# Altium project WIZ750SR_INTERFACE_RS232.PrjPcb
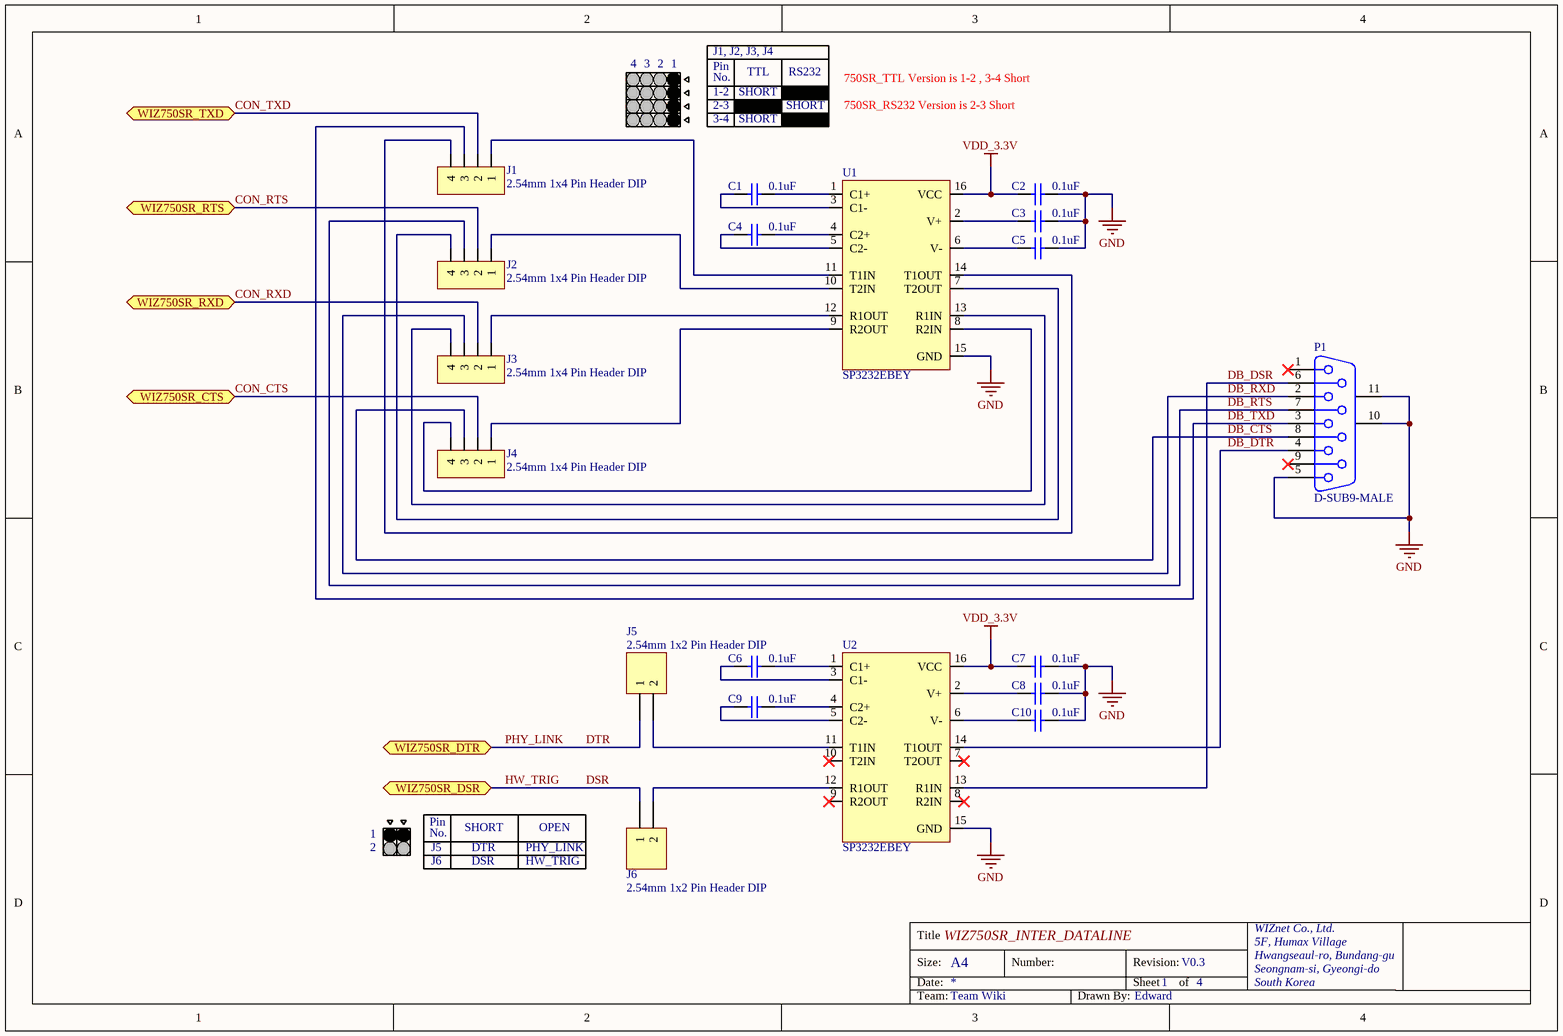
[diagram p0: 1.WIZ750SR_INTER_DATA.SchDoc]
4 sheets, 76 parts. Net scope: flat (ports and power ports of the same name join across sheets).
Board file: WIZ750SR_INTERFACE_RS232.PcbDoc
Sheets:
  1.WIZ750SR_INTER_DATA.SchDoc
  2.WIZ750SR_INTER_PWR_USB.SchDoc
  3.WIZ750SR_INTER_CON.SchDoc
  4.WIZ750SR_INTER_ETC.SchDoc

## Sheet 1.WIZ750SR_INTER_DATA.SchDoc
size A4; DrawnBy: Peter; Organization: WIZnet Co., Ltd.; Address1: 5F, Humax Village; Address2: Hwangseaul-ro, Bundang-Gu; Address3: Seongnam-Si, Gyeonggi-Do; Address4: South Korea; Team: Wiki

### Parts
C1  0.1uF  [CAP-0603]
C2  0.1uF  [CAP-0603]
C3  0.1uF  [CAP-0603]
C4  0.1uF  [CAP-0603]
C5  0.1uF  [CAP-0603]
C6  0.1uF  [CAP-0603]
C7  0.1uF  [CAP-0603]
C8  0.1uF  [CAP-0603]
C9  0.1uF  [CAP-0603]
C10  0.1uF  [CAP-0603]
J1  2.54mm 1x4 Pin Header DIP  [IDC-1X4]
J2  2.54mm 1x4 Pin Header DIP  [IDC-1X4]
J3  2.54mm 1x4 Pin Header DIP  [IDC-1X4]
J4  2.54mm 1x4 Pin Header DIP  [IDC-1X4]
J5  2.54mm 1x2 Pin Header DIP  [IDC-1X2]
J6  2.54mm 1x2 Pin Header DIP  [IDC-1X2]
P1  D-SUB9-MALE  [D-SUB9-MALE]
U1  SP3232EBEY  [SP3232EBEY-TSSOP16]
U2  SP3232EBEY  [SP3232EBEY-TSSOP16]

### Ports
WIZ750SR_CTS, WIZ750SR_DSR, WIZ750SR_DTR, WIZ750SR_RTS, WIZ750SR_RXD, WIZ750SR_TXD

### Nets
GND: C2.2 C3.2 C5.2 C7.2 C8.2 C10.2 P1.5 P1.10(MH1) P1.11(MH2) U1.15(GND) U2.15(GND)
VDD_3.3V: C2.1 C7.1 U1.16(VCC) U2.16(VCC)
CON_CTS: J4.2 ; port WIZ750SR_CTS
CON_RTS: J2.2 ; port WIZ750SR_RTS
CON_RXD: J3.2 ; port WIZ750SR_RXD
CON_TXD: J1.2 ; port WIZ750SR_TXD
DB_CTS: J4.3 P1.8
DB_DSR: P1.6 U2.13(R1IN)
DB_DTR: P1.4 U2.14(T1OUT)
DB_RTS: J2.3 P1.7
DB_RXD: J3.3 P1.2
DB_TXD: J1.3 P1.3
DSR: J6.1 ; port WIZ750SR_DSR  [also labelled HW_TRIG]
DTR: J5.1 ; port WIZ750SR_DTR  [also labelled PHY_LINK]
NetC1_1: C1.1 U1.3(C1-)
NetC1_2: C1.2 U1.1(C1+)
NetC3_1: C3.1 U1.2(V+)
NetC4_1: C4.1 U1.5(C2-)
NetC4_2: C4.2 U1.4(C2+)
NetC5_1: C5.1 U1.6(V-)
NetC6_1: C6.1 U2.3(C1-)
NetC6_2: C6.2 U2.1(C1+)
NetC8_1: C8.1 U2.2(V+)
NetC9_1: C9.1 U2.5(C2-)
NetC9_2: C9.2 U2.4(C2+)
NetC10_1: C10.1 U2.6(V-)
NetJ1_1: J1.1 U1.11(T1IN)
NetJ1_4: J1.4 U1.14(T1OUT)
NetJ2_1: J2.1 U1.10(T2IN)
NetJ2_4: J2.4 U1.7(T2OUT)
NetJ3_1: J3.1 U1.12(R1OUT)
NetJ3_4: J3.4 U1.13(R1IN)
NetJ4_1: J4.1 U1.9(R2OUT)
NetJ4_4: J4.4 U1.8(R2IN)
NetJ5_2: J5.2 U2.11(T1IN)
NetJ6_2: J6.2 U2.12(R1OUT)

Not connected (* = marked no-connect by the designer): P1 1* 9*; U2 7(T2OUT)* 8(R2IN)* 9(R2OUT)* 10(T2IN)*

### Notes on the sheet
- 4
- 3
- 2
- 1
- Pin
- 1-2
- 2-3
- No.
- J1, J2, J3, J4
- SHORT
- TTL
- RS232
- 750SR_TTL Version is 1-2 , 3-4 Short
- 750SR_RS232 Version is 2-3 Short
- 3-4
- J5
- DTR
- PHY_LINK
- OPEN
- J6
- DSR
- HW_TRIG
- Title
- Size:
- Date:
- WIZ750SR_INTER_DATALINE
- A4
- Number:
- Revision:
- Sheet
- of
- V0.3
- WIZnet Co., Ltd.
- 5F, Humax Village
- Hwangseaul-ro, Bundang-gu
- Seongnam-si, Gyeongi-do
- South Korea
- Team:
- Team Wiki
- Drawn By:
- Edward

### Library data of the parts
C1-C10 = CAP-0603: Ceramic CAP 0603(1608)
J5 J6 = Header 2: Header, 2-Pin
P1 = D-SUB9-MALE: D-SUB-9, MALE,  Right Angle; PackageDocument: O; Positions: 9; Gender: Receptacle
U1 U2 = SP3232EBEY: True +3.0V to +5.5V RS-232 Transceivers

## Sheet 2.WIZ750SR_INTER_PWR_USB.SchDoc
size A4; DrawnBy: Peter; Organization: WIZnet Co., Ltd.; Address1: 5F, Humax Village; Address2: Hwangseaul-ro, Bundang-Gu; Address3: Seongnam-Si, Gyeonggi-Do; Address4: South Korea; Team: Wiki
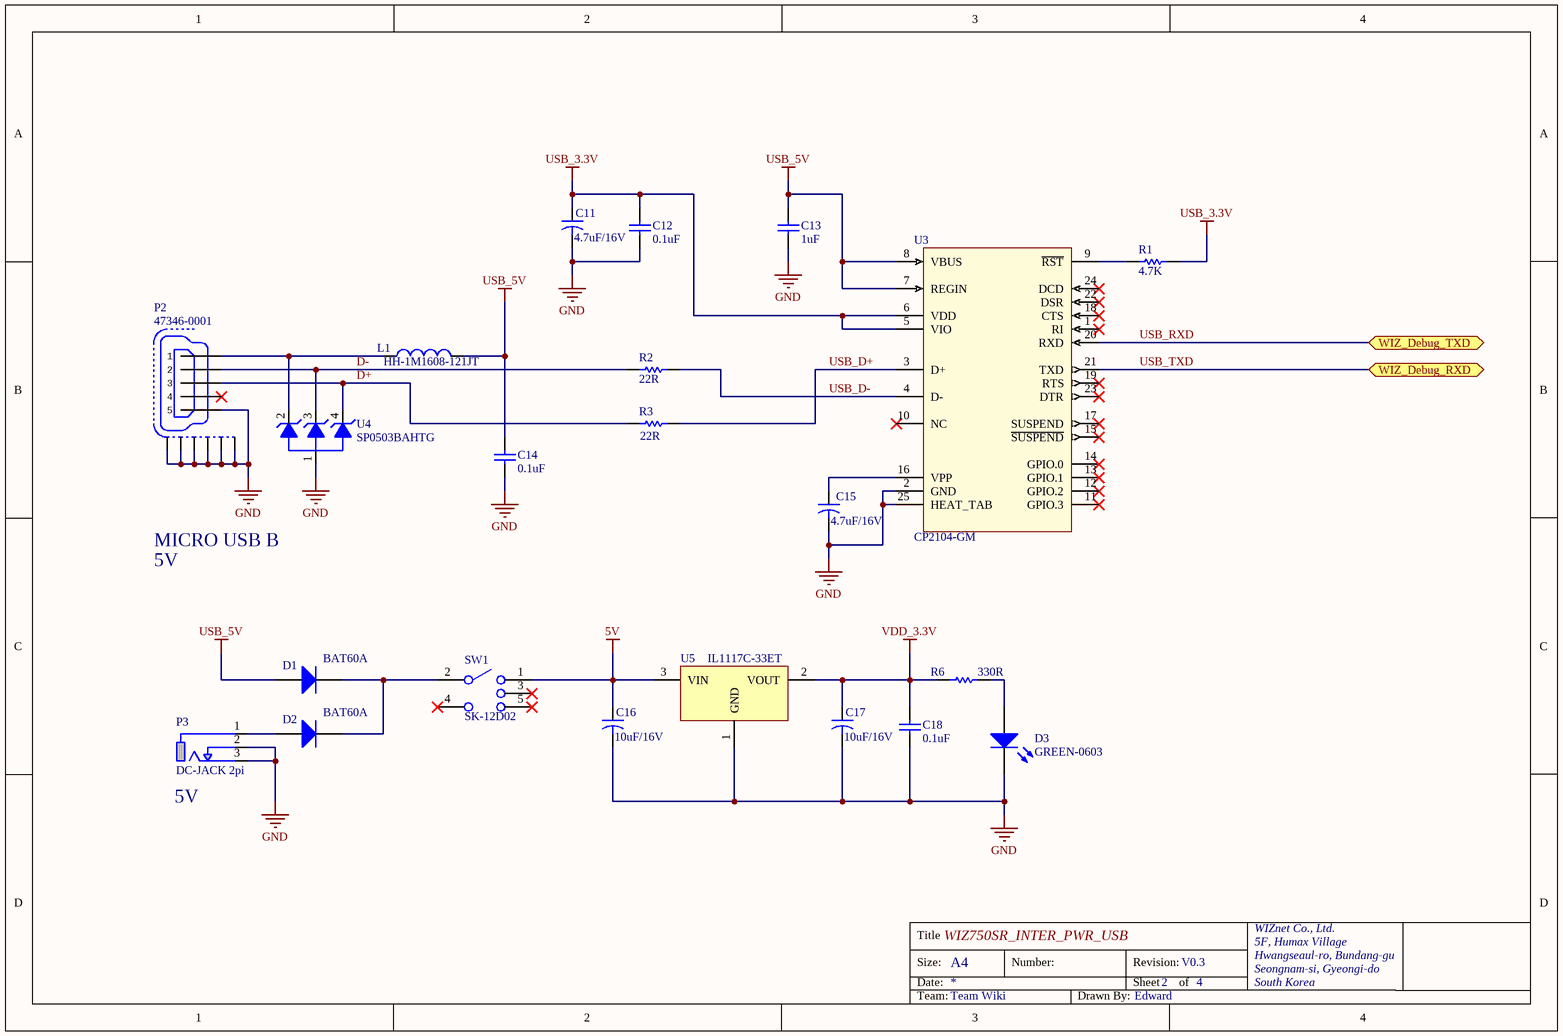
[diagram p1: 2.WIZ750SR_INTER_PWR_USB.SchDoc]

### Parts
C11  4.7uF/16V  [CAP-A Size]
C12  0.1uF  [CAP-0603]
C13  1uF  [CAP-0603]
C14  0.1uF  [CAP-0603]
C15  4.7uF/16V  [CAP-A Size]
C16  10uF/16V  [CAP-A Size]
C17  10uF/16V  [CAP-A Size]
C18  0.1uF  [CAP-0603]
D1  BAT60A  [D-BAT60A/SOD-323]
D2  BAT60A  [D-BAT60A/SOD-323]
D3  GREEN-0603  [LED-0603-RED]
L1  HH-1M1608-121JT  [IND-0603]
P2  47346-0001  [USB-MICRO-B(SMD)]
P3  DC-JACK 2pi  [DC-JACK 2pi]
R1  4.7K  [RES-0603]
R2  22R  [RES-0603]
R3  22R  [RES-0603]
R6  330R  [RES-0603]
SW1  SK-12D02  [SK-12D02]
U3  CP2104-GM  [CP2104_QFN24_PAD]
U4  SP0503BAHTG  [SP0503BAHTG]
U5  IL1117C-33ET  [IL1117C-33ET]

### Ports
WIZ_Debug_RXD, WIZ_Debug_TXD

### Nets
5V: C16.1 SW1.1 U5.3(VIN)
GND: C11.2 C12.1 C13.1 C14.1 C15.2 C16.2 C17.2 C18.1 D3.2(K) P2.5 P2.6 P2.7 P2.8 P2.9 P2.10 P2.11 P3.2(GND) P3.3(GND) U3.2(GND) U3.25(HEAT_TAB) U4.1 U5.1(GND)
USB_3.3V: C11.1 C12.2 R1.2 U3.5(VIO) U3.6(VDD)
USB_5V: C13.2 C14.2 D1.2(A) L1.2 U3.7(REGIN) U3.8(VBUS)
VDD_3.3V: C17.1 C18.2 R6.1 U5.2(VOUT)
D+: P2.3 R3.1 U4.4
D-: P2.2 R2.1 U4.3
USB_D+: R3.2 U3.3(D+)
USB_D-: R2.2 U3.4(D-)
USB_RXD: U3.20(RXD) ; port WIZ_Debug_TXD  [project net U_TXD]
USB_TXD: U3.21(TXD) ; port WIZ_Debug_RXD  [project net U_RXD]
NetC15_1: C15.1 U3.16(VPP)
NetD1_1: D1.1(K) D2.1(K) SW1.2
NetD2_2: D2.2(A) P3.1(VCC)
NetD3_1: D3.1(A) R6.2
NetL1_1: L1.1 P2.1 U4.2
NetR1_1: R1.1 U3.9(~{RST})

Not connected (* = marked no-connect by the designer): P2 4*; SW1 3* 4* 5*; U3 1(RI)* 10(NC)* 11(GPIO.3)* 12(GPIO.2)* 13(GPIO.1)* 14(GPIO.0)* 15(~{SUSPEND})* 17(SUSPEND)* 18(CTS)* 19(RTS)* 22(DSR)* 23(DTR)* 24(DCD)*

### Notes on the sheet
- MICRO USB B
- 5V
- (near P3) 5V
- Title
- Size:
- Date:
- WIZ750SR_INTER_PWR_USB
- A4
- Number:
- Revision:
- Sheet
- 2
- of
- V0.3
- 4
- WIZnet Co., Ltd.
- 5F, Humax Village
- Hwangseaul-ro, Bundang-gu
- Seongnam-si, Gyeongi-do
- South Korea
- Team:
- Team Wiki
- Drawn By:
- Edward

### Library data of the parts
C11 C15-C17 = CAP-A Size: Tantla CAP A Size EIA/IECQ 3216
C12-C14 C18 = CAP-0603: Ceramic CAP 0603(1608)
D1 D2 = DIODE-BAT60A: Silicon Schottky Diode
D3 = LED-0603
L1 = IND-0603: Inductor 0603(1608)
P2 = 47346-0001: MICRO USB B Type
R1-R3 R6 = RES-0603
SW1 = SK-12D02: 3 Port SW , SPDT ON-ON , 50V, 0.3A
U3 = CP2104-GM: USB to UART Bridge, SiliconLabs
U4 = SP0503BAHTG: Little Fuse, Silicon Protection Array Products
U5 = IL1117C-33ET: 1A, 3.3V

## Sheet 3.WIZ750SR_INTER_CON.SchDoc
size A4; DrawnBy: Peter; Organization: WIZnet Co., Ltd.; Address1: 5F, Humax Village; Address2: Hwangseaul-ro, Bundang-Gu; Address3: Seongnam-Si, Gyeonggi-Do; Address4: South Korea; Team: Wiki
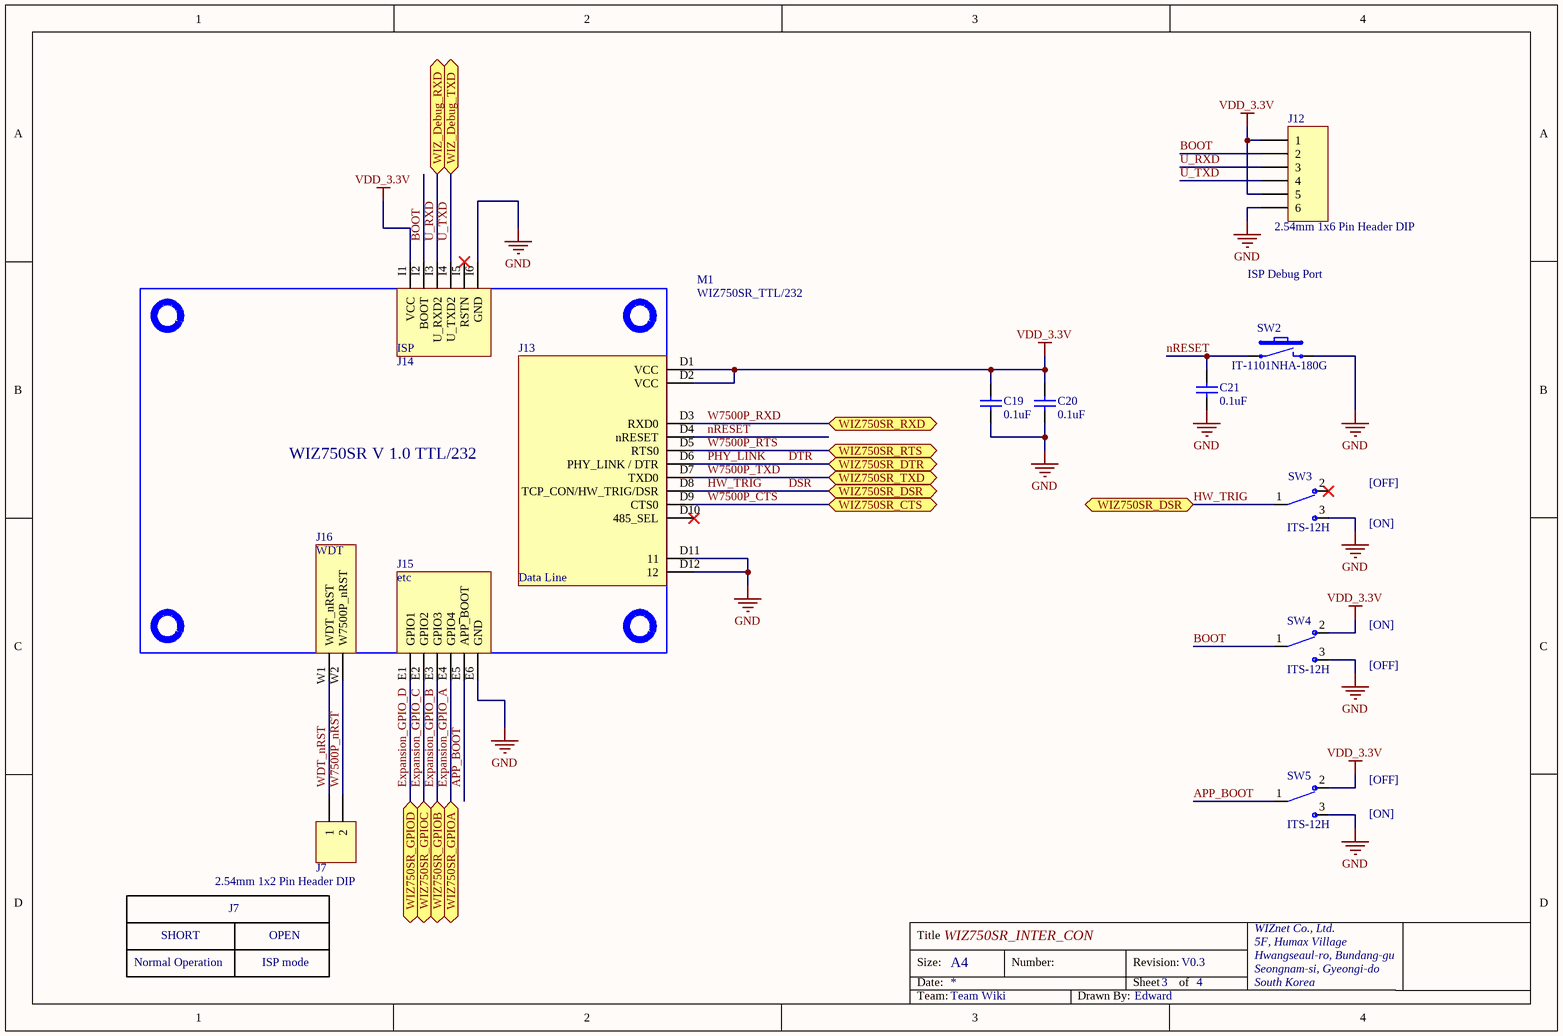
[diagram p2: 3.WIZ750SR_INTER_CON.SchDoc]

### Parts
C19  0.1uF  [CAP-0603]
C20  0.1uF  [CAP-0603]
C21  0.1uF  [CAP-0603]
J7  2.54mm 1x2 Pin Header DIP  [IDC-1X2]
J12  2.54mm 1x6 Pin Header DIP  [IDC-1X6]
M1  WIZ750SR_TTL/232  [WIZ750SR_V1.0_TTL/232]
SW2  IT-1101NHA-180G  [IT-1101NHA]
SW3  ITS-12H  [ITS-12H]
SW4  ITS-12H  [ITS-12H]
SW5  ITS-12H  [ITS-12H]

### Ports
WIZ750SR_CTS, WIZ750SR_DSR, WIZ750SR_DTR, WIZ750SR_GPIOA, WIZ750SR_GPIOB, WIZ750SR_GPIOC, WIZ750SR_GPIOD, WIZ750SR_RTS, WIZ750SR_RXD, WIZ750SR_TXD, WIZ_Debug_RXD, WIZ_Debug_TXD

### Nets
GND: C19.1 C20.1 C21.1 J12.6 M1.D11(11) M1.D12(12) M1.E6(GND) M1.I6(GND) SW2.2 SW3.3 SW4.3 SW5.3
VDD_3.3V: C19.2 C20.2 J12.1 J12.5 M1.D1(VCC) M1.D2(VCC) M1.I1(VCC) SW4.2 SW5.2
APP_BOOT: M1.E5(APP~{_}BOOT) SW5.1
BOOT: J12.2 M1.I2(BOOT) SW4.1
DSR: M1.D8(TCP_CON/HW_TRIG/DSR) SW3.1 ; port WIZ750SR_DSR  [also labelled HW_TRIG]
DTR: M1.D6(PHY_LINK_/_DTR) ; port WIZ750SR_DTR  [also labelled PHY_LINK]
Expansion_GPIO_A: M1.E4(GPIO4) ; port WIZ750SR_GPIOA
Expansion_GPIO_B: M1.E3(GPIO3) ; port WIZ750SR_GPIOB
Expansion_GPIO_C: M1.E2(GPIO2) ; port WIZ750SR_GPIOC
Expansion_GPIO_D: M1.E1(GPIO1) ; port WIZ750SR_GPIOD
nRESET: C21.2 M1.D4(nRESET) SW2.1
U_RXD: J12.3 M1.I3(U_RXD2) ; port WIZ_Debug_RXD
U_TXD: J12.4 M1.I4(U_TXD2) ; port WIZ_Debug_TXD
W7500P_CTS: M1.D9(CTS0) ; port WIZ750SR_CTS  [project net CON_CTS]
W7500P_nRST: J7.2 M1.W2(W7500P_nRST)
W7500P_RTS: M1.D5(RTS0) ; port WIZ750SR_RTS  [project net CON_RTS]
W7500P_RXD: M1.D3(RXD0) ; port WIZ750SR_RXD  [project net CON_RXD]
W7500P_TXD: M1.D7(TXD0) ; port WIZ750SR_TXD  [project net CON_TXD]
WDT_nRST: J7.1 M1.W1(WDT_nRST)

Not connected (* = marked no-connect by the designer): M1 D10(485_SEL)* I5(RSTN)*; SW3 2*

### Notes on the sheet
- ISP Debug Port
- (near M1) J14
- (near M1) J13
- [OFF]
- (near M1) J16
- (near M1) J15
- [ON]
- J7
- Normal Operation
- SHORT
- ISP mode
- OPEN
- Title
- Size:
- Date:
- WIZ750SR_INTER_CON
- A4
- Number:
- Revision:
- Sheet
- 3
- of
- V0.3
- 4
- WIZnet Co., Ltd.
- 5F, Humax Village
- Hwangseaul-ro, Bundang-gu
- Seongnam-si, Gyeongi-do
- South Korea
- Team:
- Team Wiki
- Drawn By:
- Edward

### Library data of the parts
C19-C21 = CAP-0603: Ceramic CAP 0603(1608)
J7 = Header 2: Header, 2-Pin
J12 = Header 6: Header, 6-Pin
M1 = WIZ750SR_V1.0_TTL/232: Serial to ethernet module, 45mmx30mm, TTL/232
SW2 = IT-1101NHA-180G: TACT Switch (SMD)
SW3-SW5 = ITS-12H: Slide Switch

## Sheet 4.WIZ750SR_INTER_ETC.SchDoc
size A4; DrawnBy: Peter; Organization: WIZnet Co., Ltd.; Address1: 5F, Humax Village; Address2: Hwangseaul-ro, Bundang-Gu; Address3: Seongnam-Si, Gyeonggi-Do; Address4: South Korea; Team: Wiki
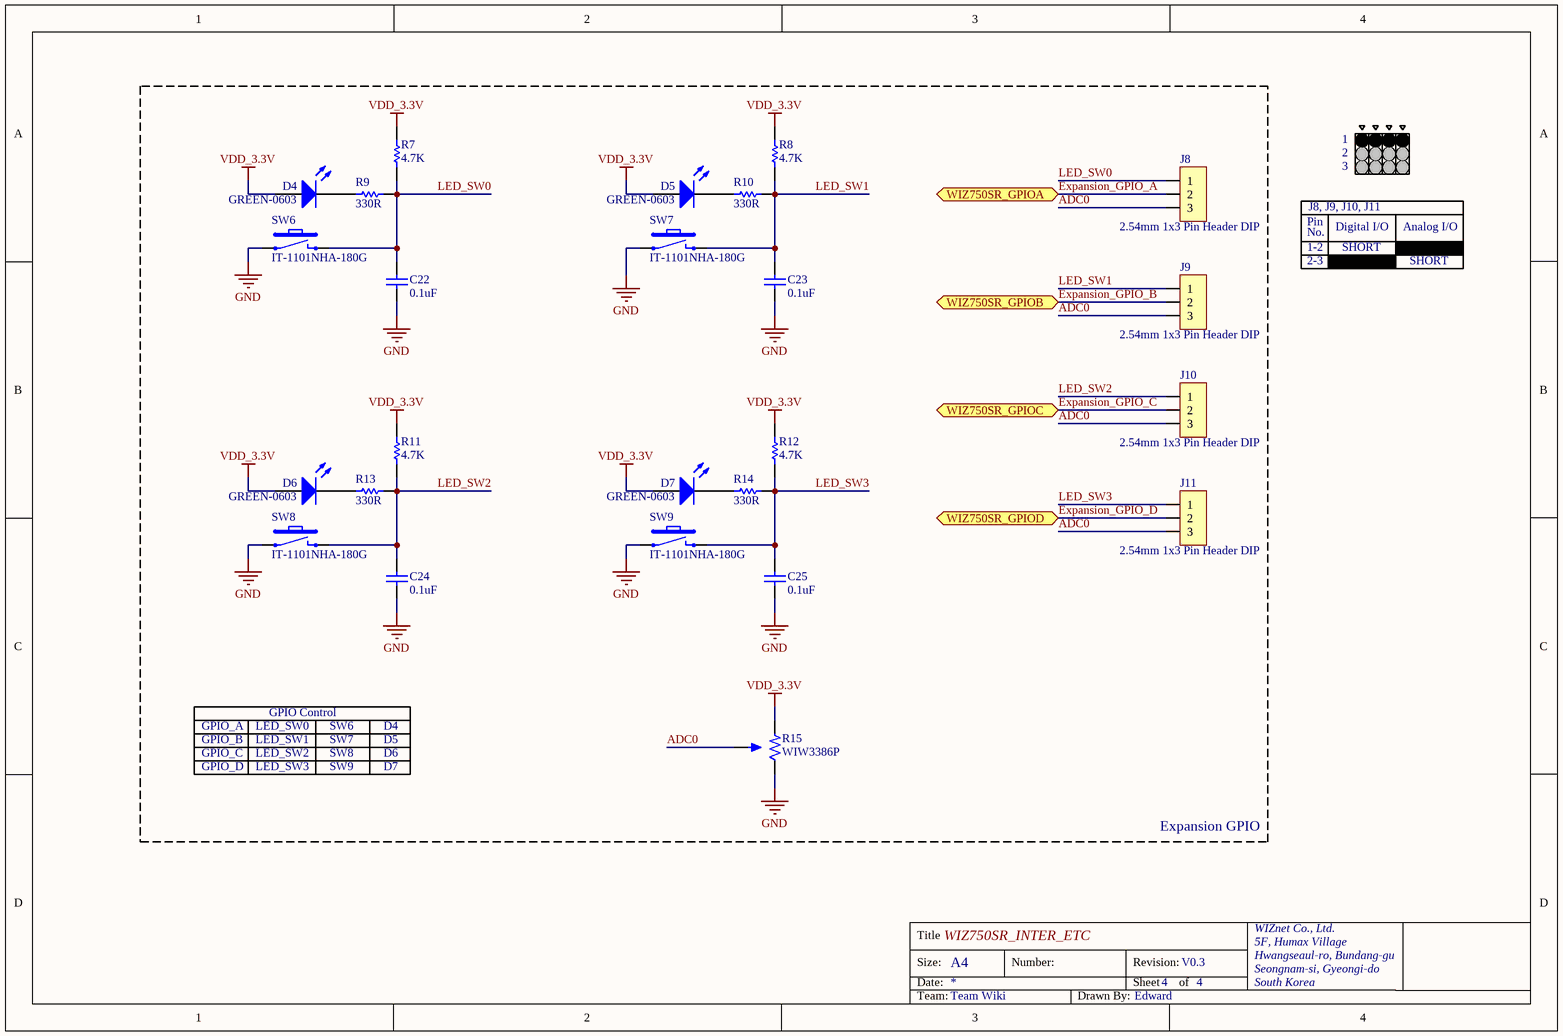
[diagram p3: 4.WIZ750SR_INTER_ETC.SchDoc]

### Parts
C22  0.1uF  [CAP-0603]
C23  0.1uF  [CAP-0603]
C24  0.1uF  [CAP-0603]
C25  0.1uF  [CAP-0603]
D4  GREEN-0603  [LED-0603-GREEN]
D5  GREEN-0603  [LED-0603-GREEN]
D6  GREEN-0603  [LED-0603-GREEN]
D7  GREEN-0603  [LED-0603-GREEN]
J8  2.54mm 1x3 Pin Header DIP  [IDC-1X3]
J9  2.54mm 1x3 Pin Header DIP  [IDC-1X3]
J10  2.54mm 1x3 Pin Header DIP  [IDC-1X3]
J11  2.54mm 1x3 Pin Header DIP  [IDC-1X3]
R7  4.7K  [RES-0603]
R8  4.7K  [RES-0603]
R9  330R  [RES-0603]
R10  330R  [RES-0603]
R11  4.7K  [RES-0603]
R12  4.7K  [RES-0603]
R13  330R  [RES-0603]
R14  330R  [RES-0603]
R15  WIW3386P  [WIW3386P]
SW6  IT-1101NHA-180G  [IT-1101NHA]
SW7  IT-1101NHA-180G  [IT-1101NHA]
SW8  IT-1101NHA-180G  [IT-1101NHA]
SW9  IT-1101NHA-180G  [IT-1101NHA]

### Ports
WIZ750SR_GPIOA, WIZ750SR_GPIOB, WIZ750SR_GPIOC, WIZ750SR_GPIOD

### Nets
GND: C22.1 C23.1 C24.1 C25.1 R15.3 SW6.1 SW7.1 SW8.1 SW9.1
VDD_3.3V: D4.1(A) D5.1(A) D6.1(A) D7.1(A) R7.2 R8.2 R11.2 R12.2 R15.1
ADC0: J8.3 J9.3 J10.3 J11.3 R15.2
Expansion_GPIO_A: J8.2 ; port WIZ750SR_GPIOA
Expansion_GPIO_B: J9.2 ; port WIZ750SR_GPIOB
Expansion_GPIO_C: J10.2 ; port WIZ750SR_GPIOC
Expansion_GPIO_D: J11.2 ; port WIZ750SR_GPIOD
LED_SW0: C22.2 J8.1 R7.1 R9.2 SW6.2
LED_SW1: C23.2 J9.1 R8.1 R10.2 SW7.2
LED_SW2: C24.2 J10.1 R11.1 R13.2 SW8.2
LED_SW3: C25.2 J11.1 R12.1 R14.2 SW9.2
NetD4_2: D4.2(K) R9.1
NetD5_2: D5.2(K) R10.1
NetD6_2: D6.2(K) R13.1
NetD7_2: D7.2(K) R14.1

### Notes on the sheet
- 3
- 2
- 1
- Pin
- 1-2
- No.
- J8, J9, J10, J11
- Digital I/O
- SHORT
- Analog I/O
- 2-3
- GPIO Control
- GPIO_A
- GPIO_B
- GPIO_C
- GPIO_D
- LED_SW0
- LED_SW1
- LED_SW2
- LED_SW3
- SW6
- SW7
- SW8
- SW9
- D4
- D5
- D6
- D7
- Expansion GPIO
- Title
- Size:
- Date:
- WIZ750SR_INTER_ETC
- A4
- Number:
- Revision:
- Sheet
- 4
- of
- V0.3
- WIZnet Co., Ltd.
- 5F, Humax Village
- Hwangseaul-ro, Bundang-gu
- Seongnam-si, Gyeongi-do
- South Korea
- Team:
- Team Wiki
- Drawn By:
- Edward

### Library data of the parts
C22-C25 = CAP-0603: Ceramic CAP 0603(1608)
D4-D7 = LED-0603
R7-R14 = RES-0603
R15 = WIW3386P: Potentiometer
SW6-SW9 = IT-1101NHA-180G: TACT Switch (SMD)

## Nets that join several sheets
GND: 1.WIZ750SR_INTER_DATA (11 pins), 2.WIZ750SR_INTER_PWR_USB (22 pins), 3.WIZ750SR_INTER_CON (12 pins), 4.WIZ750SR_INTER_ETC (9 pins)
VDD_3.3V: 1.WIZ750SR_INTER_DATA (C2.1 C7.1 U1.16 U2.16), 2.WIZ750SR_INTER_PWR_USB (C17.1 C18.2 R6.1 U5.2), 3.WIZ750SR_INTER_CON (9 pins), 4.WIZ750SR_INTER_ETC (9 pins)
CON_CTS: 1.WIZ750SR_INTER_DATA (J4.2), 3.WIZ750SR_INTER_CON (M1.D9)
CON_RTS: 1.WIZ750SR_INTER_DATA (J2.2), 3.WIZ750SR_INTER_CON (M1.D5)
CON_RXD: 1.WIZ750SR_INTER_DATA (J3.2), 3.WIZ750SR_INTER_CON (M1.D3)
CON_TXD: 1.WIZ750SR_INTER_DATA (J1.2), 3.WIZ750SR_INTER_CON (M1.D7)
DSR: 1.WIZ750SR_INTER_DATA (J6.1), 3.WIZ750SR_INTER_CON (M1.D8 SW3.1)
DTR: 1.WIZ750SR_INTER_DATA (J5.1), 3.WIZ750SR_INTER_CON (M1.D6)
Expansion_GPIO_A: 3.WIZ750SR_INTER_CON (M1.E4), 4.WIZ750SR_INTER_ETC (J8.2)
Expansion_GPIO_B: 3.WIZ750SR_INTER_CON (M1.E3), 4.WIZ750SR_INTER_ETC (J9.2)
Expansion_GPIO_C: 3.WIZ750SR_INTER_CON (M1.E2), 4.WIZ750SR_INTER_ETC (J10.2)
Expansion_GPIO_D: 3.WIZ750SR_INTER_CON (M1.E1), 4.WIZ750SR_INTER_ETC (J11.2)
U_RXD: 2.WIZ750SR_INTER_PWR_USB (U3.21), 3.WIZ750SR_INTER_CON (J12.3 M1.I3)
U_TXD: 2.WIZ750SR_INTER_PWR_USB (U3.20), 3.WIZ750SR_INTER_CON (J12.4 M1.I4)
